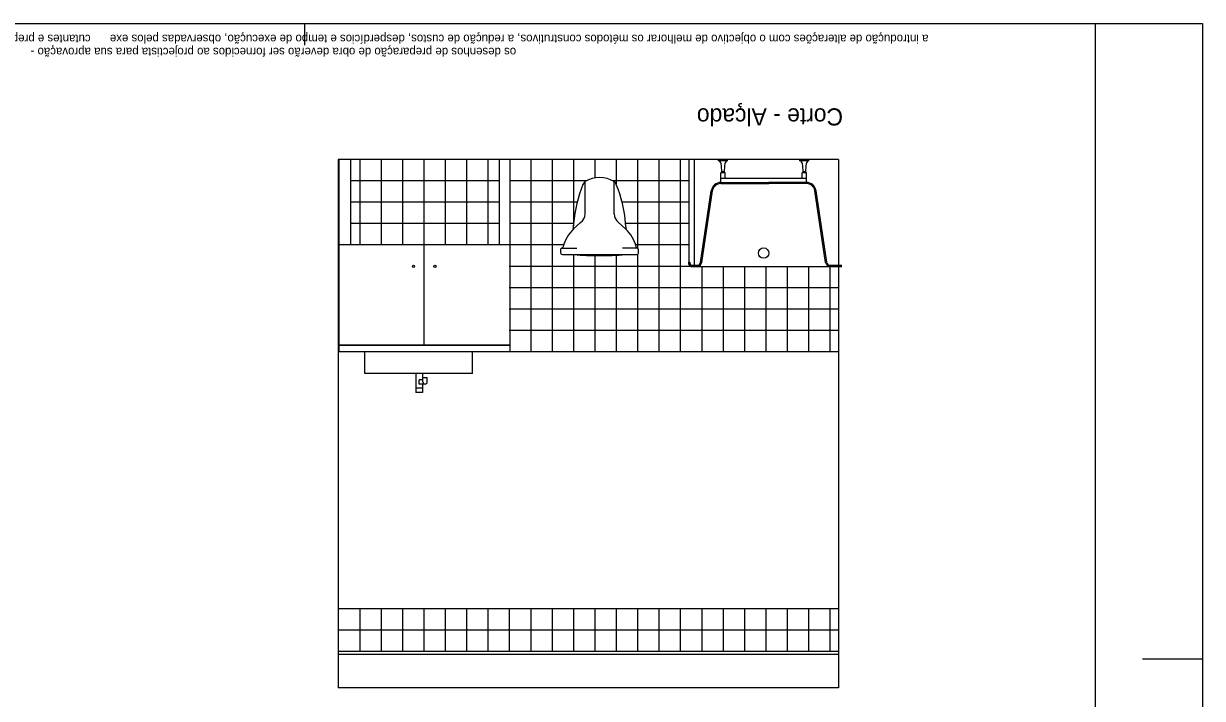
# Model space of a CAD drawing. Extents: x 1295.6 to 1307.2, y -291.8 to -285.9.
# Drawn here: x 1301.67 to 1307.18, y -289.06 to -285.9 of the extents above; entities that cross this region are included whole.
import ezdxf

# ---------------------------------------------------------------- set-up
doc = ezdxf.new("R2010")
doc.units = 0
for name, color, linetype in [('Level 1', 7, 'Continuous'), ('Level 10', 7, 'Continuous'), ('Level 11', 7, 'Continuous'), ('Level 13', 7, 'Continuous'), ('Level 2', 7, 'Continuous'), ('Level 60', 7, 'Continuous'), ('Level 62', 7, 'Continuous')]:
    doc.layers.add(name, color=color, linetype=linetype)

msp = doc.modelspace()

# ---------------------------------------------------------------- linework, layer by layer
at = {"layer": 'Level 1'}
for p, q in [((1303.1407, -286.5381), (1303.1407, -289.0081)), ((1305.4807, -286.5381), (1303.1407, -286.5381)), ((1304.7807, -286.5381), (1304.7807, -287.018)), ((1304.8057, -286.5381), (1304.8057, -287.033)), ((1305.4807, -286.5381), (1305.4807, -289.0081)), ((1304.7807, -287.018), (1304.7857, -287.018)), ((1304.7857, -287.018), (1304.7857, -287.023)), ((1304.7957, -287.033), (1304.8057, -287.033)), ((1305.4807, -288.8381), (1303.1407, -288.8381)), ((1305.4807, -288.8531), (1303.1407, -288.8531)), ((1305.4807, -289.0081), (1303.1407, -289.0081))]:
    msp.add_line(p, q, dxfattribs=at)
msp.add_arc((1304.7957, -287.023), 0.01, 180, 270, dxfattribs=at)
at = {"layer": 'Level 10'}
for p, q in [((1303.2407, -286.5381), (1303.2407, -286.9381)), ((1303.3407, -286.5381), (1303.3407, -286.9381)), ((1303.4407, -286.5381), (1303.4407, -286.9381)), ((1303.5407, -286.5381), (1303.5407, -286.9381)), ((1303.6407, -286.5381), (1303.6407, -286.9381)), ((1303.7407, -286.5381), (1303.7407, -286.9381)), ((1303.8407, -286.5381), (1303.8407, -286.9381)), ((1304.0407, -286.5381), (1304.0407, -287.4381)), ((1304.1407, -286.5381), (1304.1407, -287.4381)), ((1304.2407, -286.5381), (1304.2407, -286.8492)), ((1304.3407, -286.5381), (1304.3407, -286.6248)), ((1304.4407, -286.5381), (1304.4407, -286.6538)), ((1304.5407, -286.5381), (1304.5407, -286.9529)), ((1304.6407, -286.5381), (1304.6407, -287.4381)), ((1304.7407, -286.5381), (1304.7407, -287.4381)), ((1303.8927, -286.6381), (1303.1977, -286.6381)), ((1304.3014, -286.6381), (1303.9427, -286.6381)), ((1304.7807, -286.6381), (1304.4247, -286.6381)), ((1303.8927, -286.7381), (1303.1977, -286.7381)), ((1304.2582, -286.7381), (1303.9427, -286.7381)), ((1304.7807, -286.7381), (1304.4684, -286.7381)), ((1303.8927, -286.8381), (1303.1977, -286.8381)), ((1304.2416, -286.8381), (1303.9427, -286.8381)), ((1304.7807, -286.8381), (1304.485, -286.8381)), ((1304.1946, -286.9381), (1303.9407, -286.9381)), ((1304.6907, -286.9381), (1304.532, -286.9381)), ((1304.7807, -286.9381), (1304.6907, -286.9381)), ((1304.2407, -286.9827), (1304.2407, -287.4381)), ((1304.3407, -286.988), (1304.3407, -287.4381)), ((1304.4407, -286.9858), (1304.4407, -287.4381)), ((1304.5407, -286.9823), (1304.5407, -287.4381)), ((1304.6907, -287.0381), (1303.9407, -287.0381)), ((1304.7908, -287.0381), (1304.6907, -287.0381)), ((1304.8407, -287.0381), (1304.8407, -287.4381)), ((1304.9407, -287.0381), (1304.9407, -287.4381)), ((1305.0407, -287.0381), (1305.0407, -287.4381)), ((1305.1407, -287.0381), (1305.1407, -287.4381)), ((1305.2407, -287.0381), (1305.2407, -287.4381)), ((1305.3407, -287.0381), (1305.3407, -287.4381)), ((1305.4407, -287.0381), (1305.4407, -287.4381)), ((1304.6907, -287.1381), (1303.9407, -287.1381)), ((1305.4807, -287.1381), (1304.6907, -287.1381)), ((1304.6907, -287.2381), (1303.9407, -287.2381)), ((1305.4807, -287.2381), (1304.6907, -287.2381)), ((1304.6907, -287.3381), (1303.9407, -287.3381)), ((1305.4807, -287.3381), (1304.6907, -287.3381)), ((1303.2407, -288.6381), (1303.2407, -288.8381)), ((1303.3407, -288.6381), (1303.3407, -288.8381)), ((1303.4407, -288.6381), (1303.4407, -288.8381)), ((1303.5407, -288.6381), (1303.5407, -288.8381)), ((1303.6407, -288.6381), (1303.6407, -288.8381)), ((1303.7407, -288.6381), (1303.7407, -288.8381)), ((1303.8407, -288.6381), (1303.8407, -288.8381)), ((1303.9407, -288.6381), (1303.9407, -288.8381)), ((1304.0407, -288.6381), (1304.0407, -288.8381)), ((1304.1407, -288.6381), (1304.1407, -288.8381)), ((1304.2407, -288.6381), (1304.2407, -288.8381)), ((1304.3407, -288.6381), (1304.3407, -288.8381)), ((1304.4407, -288.6381), (1304.4407, -288.8381)), ((1304.5407, -288.6381), (1304.5407, -288.8381)), ((1304.6407, -288.6381), (1304.6407, -288.8381)), ((1304.7407, -288.6381), (1304.7407, -288.8381)), ((1304.8407, -288.6381), (1304.8407, -288.8381)), ((1304.9407, -288.6381), (1304.9407, -288.8381)), ((1305.0407, -288.6381), (1305.0407, -288.8381)), ((1305.1407, -288.6381), (1305.1407, -288.8381)), ((1305.2407, -288.6381), (1305.2407, -288.8381)), ((1305.3407, -288.6381), (1305.3407, -288.8381)), ((1305.4407, -288.6381), (1305.4407, -288.8381)), ((1305.4807, -288.7381), (1303.1407, -288.7381))]:
    msp.add_line(p, q, dxfattribs=at)
at = {"layer": 'Level 11'}
for p, q in [((1304.9612, -286.538), (1304.9199, -286.538)), ((1304.9199, -286.5447), (1304.9199, -286.538)), ((1304.9612, -286.5447), (1304.9199, -286.5447)), ((1304.9612, -286.5447), (1304.9612, -286.538)), ((1305.3415, -286.538), (1305.3002, -286.538)), ((1305.3002, -286.5447), (1305.3002, -286.538)), ((1305.3415, -286.5447), (1305.3002, -286.5447)), ((1305.3415, -286.5447), (1305.3415, -286.538)), ((1304.9301, -286.6016), (1304.935, -286.5956)), ((1304.9511, -286.6016), (1304.9301, -286.6016)), ((1304.9301, -286.6461), (1304.9301, -286.6016)), ((1305.3314, -286.628), (1304.9301, -286.628)), ((1304.9462, -286.5956), (1304.935, -286.5956)), ((1304.9511, -286.6016), (1304.9462, -286.5956)), ((1304.9511, -286.628), (1304.9511, -286.6016)), ((1305.3104, -286.6016), (1305.3153, -286.5956)), ((1305.3314, -286.6016), (1305.3104, -286.6016)), ((1305.3104, -286.628), (1305.3104, -286.6016)), ((1305.3265, -286.5956), (1305.3153, -286.5956)), ((1305.3314, -286.6016), (1305.3265, -286.5956)), ((1305.3314, -286.628), (1305.3314, -286.6016)), ((1305.3314, -286.6508), (1305.3314, -286.628)), ((1304.2958, -286.7929), (1304.2958, -286.6415)), ((1304.4308, -286.7929), (1304.4308, -286.6415)), ((1304.8357, -287.0203), (1304.8856, -286.6845)), ((1304.8408, -287.0197), (1304.8906, -286.6852)), ((1304.9301, -286.6461), (1305.1065, -286.6461)), ((1304.9301, -286.6511), (1305.1065, -286.6511)), ((1305.1065, -286.6461), (1305.155, -286.6461)), ((1305.1065, -286.6511), (1305.155, -286.6511)), ((1305.3314, -286.6461), (1305.155, -286.6461)), ((1305.3314, -286.6511), (1305.155, -286.6511)), ((1305.4208, -287.0197), (1305.3709, -286.6852)), ((1305.4258, -287.019), (1305.3759, -286.6844)), ((1304.2416, -286.8382), (1304.2373, -286.8669)), ((1304.2416, -286.8629), (1304.2744, -286.8327)), ((1304.485, -286.8629), (1304.4522, -286.8327)), ((1304.4893, -286.8669), (1304.485, -286.8382)), ((1304.1808, -286.9603), (1304.1808, -286.9749)), ((1304.1866, -286.9526), (1304.2559, -286.9526)), ((1304.54, -286.9526), (1304.4707, -286.9526)), ((1304.5458, -286.9749), (1304.5458, -286.9603)), ((1304.7807, -287.0181), (1304.7857, -287.0181)), ((1304.7807, -287.0281), (1304.7807, -287.0181)), ((1304.7857, -287.0281), (1304.7857, -287.0181)), ((1304.7907, -287.0331), (1304.8208, -287.0331)), ((1304.7907, -287.0381), (1304.8209, -287.0381)), ((1304.8207, -287.0381), (1305.4407, -287.0381)), ((1305.4407, -287.0331), (1305.4957, -287.0331)), ((1305.4407, -287.0381), (1305.4957, -287.0381)), ((1303.2645, -287.5381), (1303.2645, -287.4381)), ((1303.7689, -287.5381), (1303.7689, -287.4381)), ((1303.5041, -287.5381), (1303.5041, -287.6281)), ((1303.5341, -287.5381), (1303.5341, -287.5681)), ((1303.5366, -287.5781), (1303.5366, -287.5581)), ((1303.5366, -287.5581), (1303.5566, -287.5581)), ((1303.5566, -287.5781), (1303.5566, -287.5581)), ((1303.5041, -287.5881), (1303.5041, -287.6281)), ((1303.5341, -287.6081), (1303.5041, -287.6081)), ((1303.5341, -287.5881), (1303.5341, -287.6281)), ((1303.5341, -287.6281), (1303.5041, -287.6281))]:
    msp.add_line(p, q, dxfattribs=at)
msp.add_lwpolyline([(1304.1888, -286.9829), (1304.3658, -286.9829), (1304.5378, -286.9829)], dxfattribs=at)
msp.add_circle((1305.1307, -286.9761), 0.0242, dxfattribs=at)
for centre, radius, start, end in [((1304.9136, -286.5618), 0.0182, 10.7191, 69.4889), ((1304.7353, -286.5956), 0.1997, 0, 10.7193), ((1305.146, -286.5956), 0.1997, 169.2806, 180), ((1304.9677, -286.5618), 0.0182, 110.5106, 169.2809), ((1305.2938, -286.5618), 0.0182, 10.7191, 69.4889), ((1305.1155, -286.5956), 0.1997, 0, 10.7193), ((1305.5262, -286.5956), 0.1997, 169.2806, 180), ((1305.3479, -286.5618), 0.0182, 110.5106, 169.2809), ((1304.3633, -286.754), 0.1312, 59.0523, 120.9477), ((1304.8652, -286.8904), 0.6258, 157.8783, 175.2216), ((1304.3162, -286.6682), 0.0336, 127.3751, 156.3615), ((1304.4104, -286.6682), 0.0336, 23.6385, 52.6249), ((1303.8614, -286.8904), 0.6258, 4.7784, 22.1217), ((1304.9301, -286.6911), 0.045, 90, 171.5403), ((1304.9301, -286.6911), 0.04, 89.9998, 171.54), ((1305.3314, -286.6911), 0.045, 8.4821, 90.0003), ((1305.3314, -286.6911), 0.04, 8.4823, 89.9998), ((1304.2443, -286.7908), 0.0516, 305.6694, 357.6894), ((1304.4823, -286.7908), 0.0516, 182.3106, 234.3306), ((1304.3553, -286.9863), 0.1678, 132.6634, 166.3829), ((1304.3713, -286.9863), 0.1678, 13.6171, 47.3366), ((1304.1888, -286.9603), 0.008, 106.0135, 180), ((1304.1844, -286.9449), 0.008, 286.0135, 346.3829), ((1304.5422, -286.9449), 0.008, 193.6171, 253.9865), ((1304.5377, -286.9603), 0.008, 0, 73.9865), ((1304.1888, -286.9749), 0.008, 180, 270), ((1304.3709, -285.4124), 1.5757, 265.3469, 269.6323), ((1304.3567, -285.4283), 1.5598, 270.1485, 274.6645), ((1304.5377, -286.9749), 0.008, 270, 0), ((1304.7907, -287.0281), 0.01, 179.9992, 270.0012), ((1304.7907, -287.0281), 0.005, 180.0041, 270.0002), ((1304.8208, -287.0181), 0.015, 270.0008, 351.5408), ((1304.8209, -287.0181), 0.02, 269.9996, 355.2372), ((1305.4407, -287.0181), 0.02, 184.7638, 270.0005), ((1305.4407, -287.0181), 0.015, 184.7638, 270.0005), ((1303.5466, -287.5781), 0.01, 180, 0)]:
    msp.add_arc(centre, radius, start, end, dxfattribs=at)
at = {"layer": 'Level 13'}
for p, q in [((1303.1427, -286.5381), (1303.1427, -287.4381)), ((1303.1977, -286.5381), (1303.1977, -286.9381)), ((1303.8927, -286.5381), (1303.8927, -286.9381)), ((1303.9427, -286.5381), (1303.9427, -287.4381)), ((1303.9427, -286.9381), (1303.1407, -286.9381)), ((1303.5427, -287.4061), (1303.5427, -286.9381)), ((1303.9427, -287.4081), (1303.1407, -287.4081)), ((1303.9427, -287.4381), (1303.1407, -287.4381)), ((1303.9427, -287.4061), (1303.1427, -287.4061)), ((1303.7689, -287.5381), (1303.2645, -287.5381))]:
    msp.add_line(p, q, dxfattribs=at)
for centre in [(1303.4927, -287.0381), (1303.5927, -287.0381)]:
    msp.add_circle(centre, 0.005, dxfattribs=at)
at = {"layer": 'Level 2'}
for p, q in [((1304.6907, -287.4381), (1303.9407, -287.4381)), ((1305.4807, -287.4381), (1304.6907, -287.4381)), ((1303.5191, -287.5881), (1303.5191, -287.5681)), ((1303.5366, -287.5681), (1303.5191, -287.5681)), ((1303.5466, -287.5881), (1303.5191, -287.5881)), ((1305.4807, -288.6381), (1303.1407, -288.6381))]:
    msp.add_line(p, q, dxfattribs=at)
at = {"layer": 'Level 62'}
for p, q in [((1302.9839, -286.0034), (1302.9839, -285.9034)), ((1306.6835, -291.8434), (1306.6835, -285.9034)), ((1307.1835, -288.8734), (1306.9035, -288.8734))]:
    msp.add_line(p, q, dxfattribs=at)
msp.add_lwpolyline([(1307.1835, -285.9034), (1307.1835, -291.8434), (1295.5839, -291.8434), (1295.5839, -285.9034)], close=True, dxfattribs=at)

# ---------------------------------------------------------------- texts
at = {"layer": 'Level 60'}
msp.add_text('Corte - Alçado', height=0.08, rotation=180, dxfattribs=at).set_placement((1305.5021, -286.2994))
at = {"layer": 'Level 62'}
for s, height, p in [('cutantes e preparadores da obra deverão ser sugeridas. não poderão no entanto ser implementadas sem o consentimento expresso dos responsáveis pela arquitectura', 0.0399996, (1301.9819, -285.9554)), ('a introdução de alterações com o objectivo de melhorar os métodos construtivos, a redução de custos, desperdícios e tempo de execução, observadas pelos exe', 0.0399996, (1305.9017, -285.9554)), ('os desenhos de preparação de obra deverão ser fornecidos ao projectista para sua aprovação -', 0.04, (1303.9727, -286.0164))]:
    msp.add_text(s, height=height, rotation=180, dxfattribs=at).set_placement(p)

doc.saveas('drawing.dxf')
